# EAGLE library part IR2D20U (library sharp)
24-ch LED Driver IC Source: http://document.sharpsma.com/files/IR2D20U.pdf
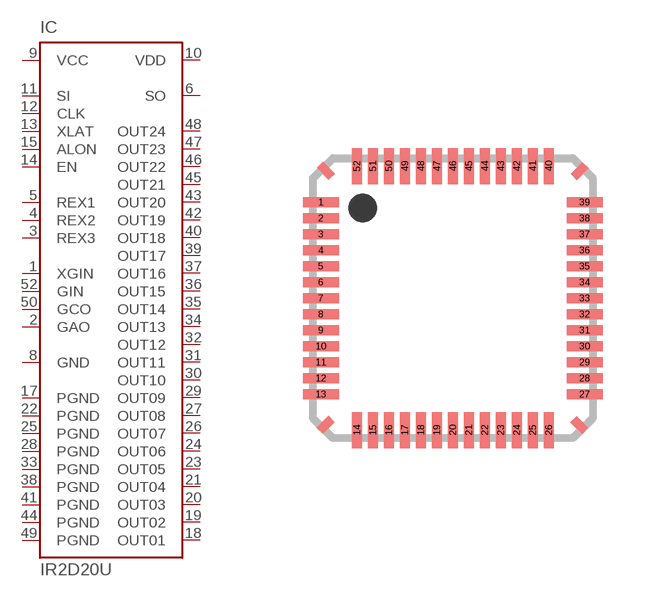
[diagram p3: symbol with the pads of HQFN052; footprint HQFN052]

Designator prefix IC

## IR2D20U (OC_FARNELL: unknown; OC_NEWARK: unknown)  [HQFN052]
1  XGIN  in
2  GAO  in
3  REX3  in
4  REX2  in
5  REX1  in
6  SO  out
8  GND  pwr
9  VCC  pwr
10  VDD  pwr
11  SI  in
12  CLK  in
13  XLAT  in
14  EN  in
15  ALON  in
17  PGND  pwr
18  OUT01  out
19  OUT02  out
20  OUT03  out
21  OUT04  out
22  PGND  pwr
23  OUT05  out
24  OUT06  out
25  PGND  pwr
26  OUT07  out
27  OUT08  out
28  PGND  pwr
29  OUT09  out
30  OUT10  out
31  OUT11  out
32  OUT12  out
33  PGND  pwr
34  OUT13  out
35  OUT14  out
36  OUT15  out
37  OUT16  out
38  PGND  pwr
39  OUT17  out
40  OUT18  out
41  PGND  pwr
42  OUT19  out
43  OUT20  out
44  PGND  pwr
45  OUT21  out
46  OUT22  out
47  OUT23  out
48  OUT24  out
49  PGND  pwr
50  GCO  in
52  GIN  in

## Footprint HQFN052 (pad centres in mm)
HQFN052-P-0707 Source: http://document.sharpsma.com/files/IR2D20U.pdf
smd 0.9 x 0.25: 1 -3.3,2.4; 2 -3.3,2; 3 -3.3,1.6; 4 -3.3,1.2; 5 -3.3,0.8; 6 -3.3,0.4; 7 -3.3,0; 8 -3.3,-0.4; 9 -3.3,-0.8; 10 -3.3,-1.2; 11 -3.3,-1.6; 12 -3.3,-2; 13 -3.3,-2.4; 27 3.3,-2.4; 28 3.3,-2; 29 3.3,-1.6; 30 3.3,-1.2; 31 3.3,-0.8; 32 3.3,-0.4; 33 3.3,0; 34 3.3,0.4; 35 3.3,0.8; 36 3.3,1.2; 37 3.3,1.6; 38 3.3,2; 39 3.3,2.4
smd 0.25 x 0.9: 14 -2.4,-3.3; 15 -2,-3.3; 16 -1.6,-3.3; 17 -1.2,-3.3; 18 -0.8,-3.3; 19 -0.4,-3.3; 20 0,-3.3; 21 0.4,-3.3; 22 0.8,-3.3; 23 1.2,-3.3; 24 1.6,-3.3; 25 2,-3.3; 26 2.4,-3.3; 40 2.4,3.3; 41 2,3.3; 42 1.6,3.3; 43 1.2,3.3; 44 0.8,3.3; 45 0.4,3.3; 46 0,3.3; 47 -0.4,3.3; 48 -0.8,3.3; 49 -1.2,3.3; 50 -1.6,3.3; 51 -2,3.3; 52 -2.4,3.3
